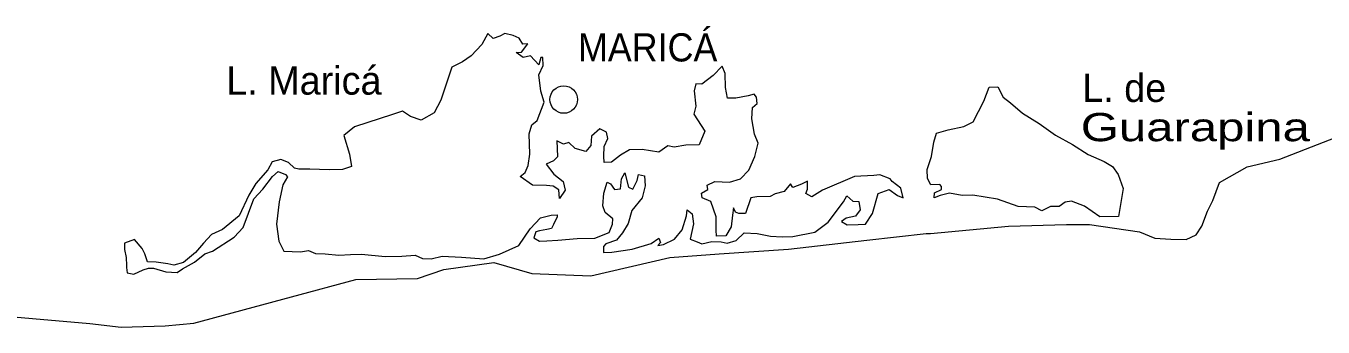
# Model space of a CAD drawing. Extents: x 47169 to 972804, y 7447977 to 9608469.
# Drawn here: x 95828 to 124798, y 7454198 to 7460931 of the extents above; entities that cross this region are included whole.
import ezdxf

# ---------------------------------------------------------------- set-up
doc = ezdxf.new("R2010")
doc.units = 0
doc.header["$LTSCALE"] = 270
doc.layers.add('1', color=7, linetype='Continuous', lineweight=13)
doc.layers.add('2', color=7, linetype='Continuous', lineweight=13)
doc.layers.add('3', color=7, linetype='Continuous')

msp = doc.modelspace()

# ---------------------------------------------------------------- linework, layer by layer
at = {"layer": '1'}
for points in [[(106866.2, 7457562), (106976.8, 7457653.7), (107044.6, 7457810.8), (107079.1, 7458066.9), (107067.2, 7458521.4), (107123.6, 7458722.6), (107244.5, 7458814.5), (107398.2, 7459229.1), (107330.2, 7459471.4), (107279.6, 7459836.2), (107376.8, 7460049.5), (107372.2, 7460226.9), (107331.1, 7460225.9), (107284.1, 7460058.2), (107093.7, 7460264), (106930.2, 7460226.5), (106773.3, 7460333.4), (106896.2, 7460347.7), (107035.4, 7460528.8), (106922.4, 7460525.9), (106847.1, 7460657), (106711.8, 7460720.1), (106525.8, 7460759.6), (106414.2, 7460701.2), (106261.3, 7460652.8), (106145.4, 7460760.8), (106008, 7460513.1), (105767.9, 7460262.7), (105576.2, 7460124.5), (105342.9, 7460007.5), (105095, 7459268.7), (104948.2, 7458987.5), (104654.5, 7458824.5), (104415.9, 7458907), (104238.2, 7459024.3), (104014, 7458951.9), (103168.2, 7458674.4), (102926.7, 7458479.4), (103050.8, 7458061.1), (103099.2, 7457785), (102895.3, 7457724.1), (102597.5, 7457716.2), (102165.6, 7457727), (101918.8, 7457731.6), (101825.8, 7457751.3), (101688.8, 7457880.9), (101522.7, 7457943), (101328.7, 7457893.5), (101230.7, 7457713.4), (100961.4, 7457406.7), (100803.8, 7457147.3), (100590, 7456686.7), (100218, 7456377.2), (99974.2, 7456270.9), (99794.4, 7456077.5), (99615.1, 7455861.9), (99343.5, 7455643.8), (99129.3, 7455582.6), (98994.9, 7455612.3), (98737.1, 7455649.8), (98541.7, 7455655.7), (98485.6, 7455831.8), (98420.7, 7455952.1), (98250.8, 7456158.4), (98026.9, 7456074.7), (98030.8, 7455930.6), (98066.4, 7455754), (98071.1, 7455576.6), (98072.3, 7455532.2), (98085.8, 7455410.5), (98240.7, 7455381.4), (98443.7, 7455475.6), (98566.1, 7455512.1), (98679, 7455515.1), (98948.3, 7455433.5), (99205.6, 7455418.2), (99326.8, 7455499.1), (99589.9, 7455650.4), (99821.4, 7455834.1), (99994.5, 7455894.2), (100479.4, 7456206.6), (100679.2, 7456422.8), (100919.2, 7457061.6), (101118.9, 7457277.7), (101337.5, 7457560.9), (101457.8, 7457675), (101623.9, 7457612.8), (101666.4, 7457558.5), (101568.4, 7457378.4)], [(114415.2, 7456492.5), (114579.5, 7456496.8), (114737.8, 7456733.8), (114859.9, 7457180.7), (115104.1, 7457275.7), (115292.6, 7457136.3), (115417.2, 7457084), (115370.5, 7457304.7), (115171.4, 7457454.9), (115128.9, 7457509.3), (114900.5, 7457603.3), (114767.3, 7457588.8), (114336.3, 7457566.7), (113614.7, 7457259.7), (113382.2, 7457109.5), (113246.7, 7457183.7), (113285.2, 7457284.5), (113280.7, 7457461.9), (113148.9, 7457392), (112955.5, 7457320.4), (112902.2, 7457396.7), (112762.7, 7457226.7), (112558.4, 7457177.1), (112446.9, 7457118.7), (112149.2, 7457111.1), (112016.2, 7457085.5), (111901.9, 7456738.6), (111747.9, 7456734.6), (111675.1, 7456766), (111631.5, 7456864.7), (111605, 7456697.6), (111580.8, 7456441.8), (111462.7, 7456239.1), (111247.1, 7456233.5), (111243.7, 7456366.6), (111246.2, 7456666.2), (111124.3, 7457007), (110927, 7457090.6), (110914.1, 7457190.1), (111055.9, 7457271.5), (111043, 7457371), (111215.6, 7457453.1), (111544.7, 7457439.4), (111789.5, 7457512.3), (111969.4, 7457705.5), (112105.5, 7458008.6), (112179.9, 7458310), (112102.9, 7458507.8), (112042.7, 7458850.1), (112056.7, 7459105.7), (112157.1, 7459197), (112143.1, 7459340.9), (112090, 7459406.1), (111957.4, 7459369.4), (111681.3, 7459317.9), (111496.4, 7459313.1), (111449, 7459556), (111441, 7459866.4), (111375.1, 7460031.1), (111174.9, 7459826.3), (110923, 7459631.2), (110789.2, 7459638.8), (110752.1, 7459482.5), (110791.8, 7459139.6), (110745, 7458960.9), (110991.2, 7458578.9), (110865.5, 7458276.1), (110567.7, 7458268.4), (110301.9, 7458217.2), (110167.5, 7458247), (109965.6, 7458108.6), (109594.1, 7458165.6), (109306.6, 7458158.1), (109104.1, 7458041.9), (108902.8, 7457881.4), (108738.4, 7457877.1), (108734.7, 7458021.2), (108739.5, 7458232.1), (108827.3, 7458411.9), (108792.8, 7458555.3), (108647, 7458629.2), (108455.9, 7458468.9), (108440.8, 7458257.7), (108331.3, 7458121.7), (108093.1, 7458193.1), (107956.1, 7458322.7), (107833.8, 7458286.2), (107688, 7458360.1), (107692.3, 7458193.8), (107697.2, 7458005.3), (107607.1, 7457914.2), (107444.6, 7457843.4), (107614.9, 7457614.9), (107824.6, 7457453.9), (107870.9, 7457255.4), (107742, 7457074.5), (107726.9, 7457262.7), (107601.3, 7457348.2), (107457, 7457366.6), (107138.4, 7457369.4), (106866.2, 7457562)], [(94688.5, 7454498.2), (97253, 7454278.6), (97953.8, 7454197.5), (98939.5, 7454223.9), (99574.9, 7454285.2), (101758, 7454875.8), (103196.7, 7455257.8), (104572.8, 7455282.9), (105163.4, 7455487), (106279.4, 7455638.3), (107128.3, 7455394.2), (108444.8, 7455339.8), (110211.6, 7455751.8), (111308.7, 7455835.7), (112857.4, 7455942.2), (114609.1, 7456142.5), (115930.7, 7456287.2), (116033.4, 7456289.9), (117775.7, 7456456.3), (119069.3, 7456489.1), (119583, 7456491), (120696.6, 7456330.5), (121039.3, 7456183.8), (121399.4, 7456159.6), (121738.5, 7456157), (121961.9, 7456262.5), (122090.6, 7456454.3), (122215.7, 7456790.2), (122333.1, 7457026.2), (122487.3, 7457429.4), (123105.3, 7457777.7), (123830.4, 7457951.1), (125651.8, 7458662)], [(101568.4, 7457378.4), (101486, 7456998.9), (101427.3, 7456498.1), (101478.4, 7456122.2), (101587.2, 7455892), (101957.5, 7455879.7), (102141.7, 7455906.7), (102297.5, 7455844.2), (102513.4, 7455838.9), (102812.4, 7455802.4), (103079.1, 7455820.5), (103325.5, 7455827), (103850.9, 7455774.3), (104220.6, 7455784), (104518.1, 7455802.9), (104684.4, 7455729.6), (104879.8, 7455723.7), (105124.7, 7455785.6), (105556.9, 7455763.7), (106051.2, 7455721.1), (106407.9, 7455830.3), (106834.5, 7456019), (107091.9, 7456391.9), (107321.8, 7456641.9), (107556.5, 7456703.5), (107690, 7456707), (107691.1, 7456662.7), (107613.3, 7456494.2), (107564.3, 7456404.2), (107462.2, 7456379.3), (107298.5, 7456352.9), (107216.9, 7456328.5), (107169, 7456194.2), (107294.3, 7456119.8), (107458.6, 7456124), (107704.7, 7456141.6), (108135.4, 7456175), (108535.8, 7456185.4), (108851, 7456315.6), (108928.5, 7456495.2), (108935.6, 7456617.4), (108767.6, 7456757.3), (108712.2, 7456911.2), (108735.8, 7457189.1), (108811.6, 7457435.2), (108884.3, 7457403.8), (108969.9, 7457272.9), (109103.1, 7457287.4), (109128.2, 7457510), (109206.9, 7457645.2), (109287.1, 7457325.5), (109380.7, 7457283.5), (109478.5, 7457474.7), (109505.8, 7457608.5), (109640.2, 7457578.7), (109656.2, 7457357.3), (109591.2, 7457089.3), (109362.2, 7456806), (109277.3, 7456515.3), (109149.3, 7456301.2), (109019.9, 7456142.5), (108775.4, 7456058.5), (108725.6, 7456001.7), (108729, 7455868.7), (108913.8, 7455873.5), (109364.2, 7455940.7), (109792.5, 7456062.7), (109963.9, 7456189.2), (109997.3, 7456090.2), (109937.4, 7456022.1), (110070.3, 7456047.7), (110313.9, 7456165), (110483.3, 7456369.1), (110577.9, 7456682.2), (110595, 7456815.8), (110710.2, 7456730), (110736.5, 7456508.8), (110663.3, 7456162.9), (110819, 7456100.4), (110922.8, 7456058.7), (111147.6, 7456108.9), (111353.2, 7456103.1), (111487.5, 7456073.3), (111691.4, 7456134), (111872, 7456305.1), (112160, 7456290.4), (112459.5, 7456231.5), (112716.8, 7456215.9), (112952.9, 7456222), (113443.5, 7456323.4), (113746.1, 7456541.9), (114083.8, 7456994.4), (114162.5, 7457129.5), (114299.2, 7457011), (114432.9, 7457003.3), (114458.3, 7456815.4), (114359, 7456679.7), (114144.5, 7456629.8), (114043.6, 7456560.7), (114168.8, 7456486.2), (114415.2, 7456492.5)]]:
    msp.add_lwpolyline(points, dxfattribs=at)
msp.add_lwpolyline([(118823.5, 7458490.8), (119198.7, 7458278.4), (119553.7, 7458054.4), (119907, 7457896.9), (120094.7, 7457790.7), (120222.6, 7457605.4), (120333.1, 7457297.5), (120225.6, 7456673.6), (119814.9, 7456663.2), (119469.9, 7456898.6), (119179.4, 7457013.2), (119036.2, 7456987.4), (118904.9, 7456895.4), (118709.9, 7456890.4), (118517, 7456796.8), (118360.8, 7456881.6), (117990.6, 7456894.4), (117524.1, 7457060), (116977.3, 7457146), (116741.2, 7457139.9), (116452.3, 7457188.1), (116248, 7457138.5), (116115.7, 7457090.7), (116123.1, 7457201.9), (116275.5, 7457272.3), (116273.8, 7457338.8), (116241.8, 7457382.4), (116036.5, 7457377.1), (115960.9, 7457519.4), (115955.8, 7457719), (116051.2, 7458009.9), (116104.6, 7458333), (116161.1, 7458534.1), (116426.4, 7458607.4), (116773.8, 7458682.8), (116986.9, 7458788.1), (117221.8, 7459248.9), (117337.2, 7459562.5), (117532.3, 7459567.4), (117651.2, 7459337.4), (117818.8, 7459208.6), (118081.5, 7458982.3), (118457.3, 7458747.7)], close=True, dxfattribs=at)
at = {"layer": '2'}
msp.add_circle((107838.6, 7459284.9), 308.2, dxfattribs=at)

# ---------------------------------------------------------------- texts
at = {"layer": '3'}
for s, height, width, p in [('MARICÁ', 630.6, 0.95, (108155.6, 7460136.4)), ('Guarapina', 630.4, 1.3, (119386.5, 7458353.9))]:
    msp.add_text(s, height=height, dxfattribs=dict(at, width=width)).set_placement(p)
for s, height, p in [('L. Maricá', 630.5, (100301.7, 7459394.8)), ('L. de', 630.4, (119420.1, 7459231.1))]:
    msp.add_text(s, height=height, dxfattribs=at).set_placement(p)

doc.saveas('drawing.dxf')
